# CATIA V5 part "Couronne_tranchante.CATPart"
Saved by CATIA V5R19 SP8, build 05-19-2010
Part number: Couronne_tranchante
Bounding box of the stored display mesh (mm): x -24.386 to 139.648, y 19.509 to 149.973, z 0 to 4
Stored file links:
  G:\EU_thinkMotion\CFAO_2010\MMS_groupe1\MMS_groupe1\OK\vduret\vduret\CATIA\Couronne_tranchante.CATPart
  F:\CFAO TP\Machine_de_coupe.CATProduct
  G:\EU_thinkMotion\CFAO_2010\MMS_groupe1\MMS_groupe1\OK\vduret\vduret\CATIA\Disque_porteur.CATPart
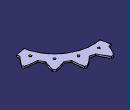
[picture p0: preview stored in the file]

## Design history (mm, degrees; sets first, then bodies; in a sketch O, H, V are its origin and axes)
External parameters (linked from other documents)
  External.Longueur_epaulement = 100 mm
  External.Nbre_dents = 16
  External.Diam_ext_disque_porteur = 300 mm
  External.Diam_int_disque_porteur = 250 mm
  External.Angle_beta = 55 deg
Body1 (main body)
  Sketch1 on xy-plane, origin (0, 0, 0), H (1, 0, 0), V (0, 1, 0)
    arc A1 centre (0, 0) radius 125 from (17.1321, 123.8204) to (-17.1321, 123.8204) ccw
    arc A2 centre (0, 0) radius 150 from (2.8503, 149.9729) to (-2.8503, 149.9729) ccw
    construction line L1 through (0, 10.86) direction (0, 1)
    construction line L2 (0, 320.86) -> (0, -158.9019)
    construction line L3 through (5.2101, 0) direction (1, 0)
    point P1 (-103.3526, 75)
    point P2 (103.3526, 75)
    point P3 (0, 158)
    construction line L4 (0, 158) -> (82.2496, 0)
    construction line L5 (-82.2496, 0) -> (0, 158)
    point P4 (82.2496, 0)
    point P5 (-82.2496, 0)
    arc A3 centre (103.3526, 75) radius 130 from (-2.8503, 149.9729) to (-17.1321, 123.8204) ccw
    axis line L6 (-140, 150) -> (150, 150)
    arc A4 centre (-103.3526, 75) radius 130 from (17.1321, 123.8204) to (2.8503, 149.9729) ccw
    point P6 (0, 0)
    point P14 (0, 320.86)
    radius A2 = 150 {= External.Diam_ext_disque_porteur  /2}
    radius A1 = 125 {= External.Diam_int_disque_porteur  /2}
    distance P1 L3 = 75 {= `détruit_Diam_ext_disque_porteur.4` /4}
    distance P2 L3 = 75 {= `détruit_Diam_ext_disque_porteur.4` /4}
    angle L5 L4 = 55 {= External.Angle_beta}
    angle L5 L2 = 27.5 {= External.Angle_beta  /2}
    distance P3 L6 = 8
    distance P1 A4 = 130
    distance P2 L5 = 130
    vertical: L2 L1
    coincidence: P3 L2, P4 L3, P5 L3, P14 L1, H L3, L2 V, P6 O
    tangency: A3 L5, L6 A2, A4 L4
    horizontal: L6 H
  Sketch2 on xy-plane, origin (0, 0, 0), H (1, 0, 0), V (0, 1, 0)
    arc A1 centre (0, 0) radius 125 from (122.5982, 24.3863) to (-24.3863, 122.5982) ccw
    reference projected arc E1 centre (0, 0) radius 125 from (17.1321, 123.8204) to (-17.1321, 123.8204) ccw from Sketch1.A1
    arc A2 centre (0, 0) radius 100 from (98.0785, 19.509) to (-19.509, 98.0785) ccw
    construction line L1 (0, 0) -> (184.8961, 36.7781)
    construction line L2 (0, 0) -> (-35.1061, 176.4904)
    construction line L3 (0, 0) -> (0, 203.7679)
    point P4 (-19.509, 98.0785)
    point P5 (98.0785, 19.509)
    line L4 (-19.509, 98.0785) -> (-24.3863, 122.5982)
    point P6 (-24.3863, 122.5982)
    line L5 (98.0785, 19.509) -> (122.5982, 24.3863)
    point P7 (122.5982, 24.3863)
    point P8 (-24.3863, 122.5982)
    point P9 (122.5982, 24.3863)
    radius A2 = 100 {= External.Longueur_epaulement}
    angle L2 L1 = 90
    angle L2 L3 = 11.25
    coincidence: A1 E1, L2 P4, L1 P5, P6 A1, P7 A1, L4 L2, L5 L1, L2 P8, L1 P9, P6 P8, P7 P9
    vertical: L3 V
    parallelism: L4 L2, L5 L1
  Pad1: profile Sketch2, direction (0, 0, 1), length 4
  Pad2: profile Sketch1, direction (0, 0, 1), length 4
  Point1: (0, 0, 0)
  Line1: type PtDir, RefPoint Point1, Direction xy-plane, Start -89, End 77
  CircPattern1: of Pad2, instances 4 {= External.Nbre_dents /4}, angular step -22.5, axis from Line1
  Point2: type OnPlane, Support face of CircPattern1, H 0, V -115 {= -External.Diam_int_disque_porteur /2+10mm}, Direction (1, 0, 0)
  Sketch3 on face of CircPattern1, origin (0, 115, 0), H (1, 0, 0), V (0, -1, 0)
    point P1 (0, 0)
    reference projected point E1 (0, 0) from Point2
    coincidence: E1 P1
  Hole1: placed by Sketch3, at (0, 115, 0) direction (0, 0, 1), diameter 6, through (limit type 3)
  CircPattern2: of Hole1, instances 4, angular step -22.5, axis from Line1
